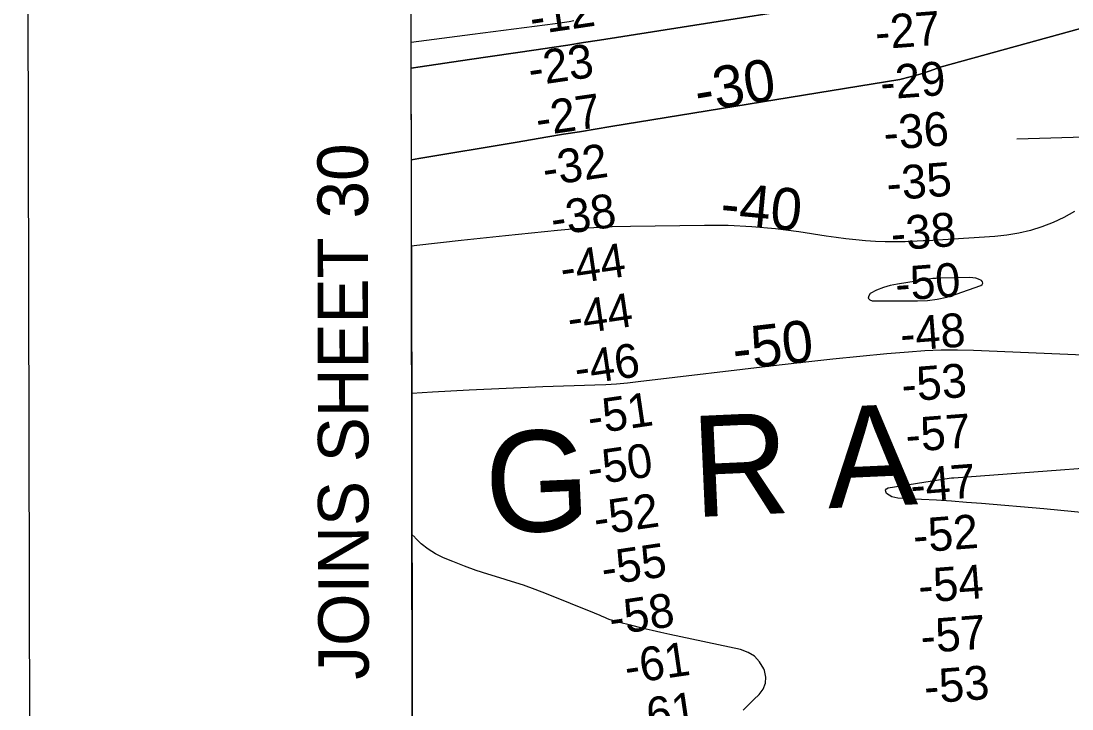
# Model space of a CAD drawing. Extents: x 3329332 to 3367211, y 631066 to 656469.
# Drawn here: x 3332666 to 3334750, y 646478 to 647841 of the extents above; entities that cross this region are included whole.
import ezdxf

# ---------------------------------------------------------------- set-up
doc = ezdxf.new("R2010")
doc.units = 0
for name, color, linetype in [('V-ANNO-SYMB', 7, 'Continuous'), ('V-ANNO-TEXT', 7, 'Continuous'), ('V-GRID-FRAM', 7, 'Continuous'), ('V-RIVR-EDGE', 7, 'Continuous'), ('V-RIVR-IDEN', 7, 'Continuous'), ('V-RIVR-RANG', 7, 'Continuous'), ('V-STRM-FLOW', 7, 'Continuous'), ('V-TOPO-DPTH', 7, 'Continuous'), ('V-TOPO-MAJR', 7, 'Continuous'), ('V-TOPO-MAJR-IDEN', 7, 'Continuous'), ('V-TOPO-MINR', 7, 'Continuous'), ('V-TOPO-MINR-IDEN', 7, 'Continuous')]:
    doc.layers.add(name, color=color, linetype=linetype)

msp = doc.modelspace()

# ---------------------------------------------------------------- linework, layer by layer
at = {"layer": 'V-ANNO-SYMB'}
msp.add_lwpolyline([(3332709.6, 632280), (3365792.7, 632342.5), (3365749.4, 655259), (3332666.3, 655196.5), (3332709.6, 632280)], dxfattribs=at)
at = {"layer": 'V-GRID-FRAM'}
msp.add_lwpolyline([(3333429.9, 654632), (3364987.9, 654691.7), (3365030.2, 636507.7), (3333456.4, 636448), (3333429.9, 654632)], dxfattribs=at)
at = {"layer": 'V-RIVR-EDGE'}
msp.add_spline([(3343636.8, 646843.4), (3343622.1, 646851.6), (3343608.9, 646858.6), (3343596.5, 646861.3), (3343585.3, 646861.8), (3343568.2, 646866.8), (3343554.7, 646877.7), (3343538.1, 646892.1), (3343529.1, 646895.6), (3343519.5, 646901.9), (3343506.7, 646910), (3343488.9, 646921.3), (3343476.1, 646929.9), (3343464.1, 646937.3), (3343456.7, 646944.3), (3343449.8, 646951.3), (3343444.7, 646953.2), (3343437.4, 646956), (3343425, 646958.3), (3343409.5, 646962.2), (3343396.7, 646968.1), (3343383.5, 646974.3), (3343375.8, 646976.7), (3343358.7, 646980.2), (3343342.4, 646984.1), (3343325, 646985.3), (3343315.3, 646986.5), (3343304.8, 646990.4), (3343289, 646998.6), (3343275.4, 647006.8), (3343265, 647012.6), (3343248.7, 647018.5), (3343234, 647022.4), (3343209.9, 647028.3), (3343162.3, 647042.4), (3343147.9, 647045.1), (3343128.9, 647049.4), (3343116.5, 647051.8), (3343106.5, 647056.8), (3343102.6, 647058.8), (3343086.7, 647062.3), (3343081.3, 647062.3), (3343073.5, 647063.9), (3343064.6, 647066.2), (3343053.7, 647071.7), (3343047.9, 647075.6), (3343041.7, 647078.3), (3343029.3, 647083), (3343020, 647087.7), (3343006.5, 647095.1), (3342971.6, 647108), (3342951.5, 647116.6), (3342937.2, 647125.1), (3342928.2, 647130.6), (3342903.1, 647138.8), (3342877.5, 647148.5), (3342858.9, 647157.5), (3342849.6, 647166.1), (3342844.2, 647170.7), (3342831.8, 647175.4), (3342823.7, 647177.8), (3342803.9, 647181.7), (3342796.5, 647184.4), (3342787.2, 647189.5), (3342775.6, 647194.6), (3342758.9, 647198.9), (3342733, 647203.6), (3342721.3, 647205.9), (3342697.7, 647211.8), (3342664, 647222), (3342635.7, 647232.1), (3342620.6, 647237.2), (3342602, 647239.2), (3342563.6, 647249.4), (3342526.8, 647258.8), (3342490.8, 647270.9), (3342457.1, 647284.1), (3342444.7, 647290), (3342438, 647274.1), (3342415.2, 647281.5), (3342391.9, 647292.1), (3342329.2, 647319.8), (3342295.1, 647333.8), (3342283.1, 647338.9), (3342254.8, 647352.1), (3342236.2, 647360.3), (3342218.4, 647367.3), (3342205.2, 647372.8), (3342191.6, 647379.4), (3342179.3, 647387.6), (3342172.3, 647390.7), (3342149.8, 647402), (3342116.9, 647419.2), (3342096.4, 647427.4), (3342074.7, 647436.7), (3342056.5, 647442.2), (3342048.7, 647445.3), (3342046.4, 647448), (3342044.5, 647450.4), (3342038.3, 647452.7), (3342007.6, 647462.5), (3341964.2, 647476.9), (3341952.2, 647483.6), (3341946, 647485.5), (3341937.1, 647486.3), (3341928.6, 647486.7), (3341922.4, 647489.8), (3341906.5, 647496.5), (3341894.5, 647501.9), (3341878.2, 647510.1), (3341870.1, 647509.7), (3341856.9, 647512.1), (3341848, 647514.5), (3341827.1, 647520.3), (3341821.3, 647523.4), (3341814.7, 647526.6), (3341810, 647526.6), (3341806.5, 647525.8), (3341795.3, 647527), (3341774.7, 647530.5), (3341748.8, 647539.9), (3341739.1, 647543.8), (3341723.2, 647545.8), (3341703.4, 647550.1), (3341688.7, 647553.2), (3341675.1, 647556.4), (3341665.1, 647559.5), (3341655.8, 647566.5), (3341650.4, 647570.8), (3341641.1, 647573.1), (3341619.4, 647577.5), (3341603.1, 647581), (3341588.7, 647581), (3341577.9, 647580.3), (3341570.5, 647581.8), (3341563.9, 647584.6), (3341550.4, 647590.8), (3341537.2, 647595.5), (3341512, 647602.9), (3341494.2, 647606.9), (3341474, 647611.9), (3341452.3, 647619.4), (3341435.6, 647623.7), (3341426.7, 647624.1), (3341409.7, 647627.6), (3341399.6, 647628.4), (3341382.2, 647633.9), (3341364.3, 647640.9), (3341355.4, 647643.3), (3341344.2, 647645.2), (3341336, 647644.9), (3341320.5, 647646.4), (3341290.7, 647651.2), (3341274, 647656.3), (3341268.6, 647656.7), (3341257, 647656.3), (3341232.5, 647658.7), (3341212, 647661.8), (3341186, 647668.9), (3341159.7, 647674), (3341146.5, 647674.8), (3341117, 647677.6), (3341103.4, 647677.2), (3341097.6, 647677.2), (3341091.8, 647678.8), (3341087.9, 647680.8), (3341085.2, 647682.7), (3341079.8, 647684.7), (3341055.4, 647685.9), (3341036.4, 647687.5), (3341024.7, 647686), (3341011.2, 647684.8), (3340999.5, 647686.8), (3340985.2, 647690.3), (3340953.8, 647701.3), (3340935.6, 647709.1), (3340923.6, 647714.5), (3340917, 647718.4), (3340910.8, 647718.4), (3340908.1, 647717.3), (3340903.8, 647717.3), (3340894.5, 647718.5), (3340882.5, 647719.3), (3340860.8, 647726.3), (3340855.8, 647729.8), (3340851.9, 647734.5), (3340848.4, 647736.8), (3340842.6, 647737.6), (3340826.3, 647742.3), (3340811.6, 647748.9), (3340794.9, 647758.7), (3340781.4, 647769.2), (3340774.8, 647778.9), (3340770.9, 647778.9), (3340766.3, 647782), (3340765.2, 647787.8), (3340765.2, 647791.3), (3340761.7, 647794.8), (3340748.9, 647800.7), (3340736.9, 647803.8), (3340725.3, 647807.3), (3340719.4, 647809.6), (3340716.4, 647813.1), (3340707.8, 647818.2), (3340686.5, 647829.9), (3340661, 647840.4), (3340654.4, 647842.4), (3340636.6, 647848.2), (3340626.5, 647851), (3340619.1, 647851), (3340608.2, 647849.1), (3340603.2, 647848.7), (3340600.5, 647851.1), (3340597.8, 647853.8), (3340589.6, 647855.3), (3340581.5, 647857.7), (3340569.1, 647863.9), (3340561.4, 647869), (3340557.9, 647873.6), (3340534.6, 647880.7), (3340500.5, 647891.6), (3340470.7, 647900.2), (3340445.5, 647911.2), (3340419.6, 647920.5), (3340404.1, 647927.5), (3340372.7, 647939.6), (3340342.5, 647952.9), (3340306.1, 647969.7), (3340282.8, 647985.6), (3340275.1, 647994.2), (3340268.9, 647998.8), (3340258.8, 648001.2), (3340240.2, 648007.1), (3340208.8, 648017.2), (3340162.7, 648036.7), (3340150.3, 648044.9), (3340132.9, 648056.2), (3340120.1, 648064.4), (3340103.9, 648071.8), (3340062.4, 648085.1), (3340020.6, 648097.2), (3340008.2, 648099.9), (3339970.6, 648113.2), (3339931.4, 648129.2), (3339890, 648138.2), (3339851.6, 648144.1), (3339826.8, 648151.2), (3339779.1, 648166), (3339750.5, 648177), (3339726.4, 648186.7), (3339710.2, 648194.1), (3339698.6, 648200), (3339685, 648204.7), (3339657.5, 648210.2), (3339640.4, 648209.4), (3339598.1, 648212.2), (3339566.4, 648218.9), (3339519.1, 648229.1), (3339492.7, 648236.9), (3339468.3, 648244.8), (3339451.6, 648247.9), (3339423.7, 648249.9), (3339391.1, 648250.4), (3339356.3, 648256.7), (3339323.3, 648262.2), (3339267.1, 648267), (3339191.5, 648276.1), (3339142.6, 648283.6), (3339080.6, 648294.2), (3339050, 648300.1), (3339012.8, 648305.2), (3338936.4, 648315.1), (3338861.6, 648324.6), (3338841, 648325.8), (3338779.4, 648333.3), (3338717, 648341.2), (3338619.7, 648351.2), (3338573.9, 648357.9), (3338540.2, 648363.4), (3338502.2, 648370.5), (3338454.1, 648371.4), (3338406, 648373.4), (3338372.7, 648373.9), (3338327.7, 648378.3), (3338302.9, 648381.4), (3338283.5, 648380.7), (3338273.8, 648381.5), (3338260.7, 648386.6), (3338248.6, 648391.6), (3338238.6, 648396.3), (3338223.5, 648397.5), (3338149.4, 648404.7), (3338106.8, 648411), (3338090.5, 648416.9), (3338075.8, 648425.4), (3338068, 648428.5), (3338061, 648430.1), (3338050.2, 648432.5), (3338042.1, 648437.1), (3338023.1, 648446.5), (3338014.2, 648455.1), (3338009.5, 648464.4), (3338008, 648470.6), (3338005.7, 648475.6), (3338000.3, 648481.5), (3337993.3, 648485), (3337977.8, 648485), (3337963.8, 648486.6), (3337952.2, 648492.4), (3337934.8, 648503.3), (3337924.4, 648514.6), (3337915.5, 648527.8), (3337907, 648538.3), (3337897.7, 648544.1), (3337885.7, 648546.1), (3337868.6, 648552.4), (3337833.7, 648570.3), (3337831.4, 648572.6), (3337828.3, 648579.6), (3337825.3, 648586.6), (3337821.8, 648591.3), (3337805.1, 648601.8), (3337772.2, 648615.4), (3337745.1, 648623.2), (3337725.3, 648627.6), (3337697.4, 648633.4), (3337655.9, 648643.2), (3337633.1, 648645.2), (3337587.7, 648647.3), (3337530.7, 648646.3), (3337482.2, 648645.6), (3337469.4, 648646), (3337459.3, 648649.5), (3337449.6, 648650.7), (3337426, 648650.8), (3337387.2, 648648.6), (3337346.1, 648646), (3337294.5, 648642.2), (3337235.9, 648635), (3337203.7, 648632), (3337180.8, 648629.7), (3337120.3, 648621.3), (3337079.6, 648613.3), (3337042, 648609.5), (3337018.3, 648606.8), (3336982.6, 648599.1), (3336951.6, 648594.2), (3336908.5, 648592.7), (3336875.2, 648597.1), (3336858.1, 648598.3), (3336851.1, 648601), (3336844.9, 648603.4), (3336839.1, 648604.2), (3336831, 648604.2), (3336822, 648601.1), (3336811.6, 648595.3), (3336803, 648593.4), (3336796, 648593), (3336789.1, 648595.4), (3336779.4, 648595.8), (3336757.3, 648590.8), (3336729.7, 648577.7), (3336702.1, 648570), (3336685.9, 648570.4), (3336673.8, 648572), (3336663.7, 648571.2), (3336652.9, 648568.2), (3336637, 648559.3), (3336627.3, 648556.6), (3336614.5, 648555.9), (3336585, 648551.7), (3336546.2, 648547.9), (3336510.1, 648542.1), (3336477.9, 648535.2), (3336448.4, 648524.8), (3336423.9, 648508.6), (3336410.7, 648494.7), (3336400.6, 648480.4), (3336397.5, 648469.1), (3336394.7, 648454), (3336388.1, 648437.7), (3336381.5, 648423.4), (3336376, 648411), (3336372.5, 648404), (3336364.3, 648397.9), (3336361.2, 648394.8), (3336359.7, 648392.1), (3336357.7, 648385.9), (3336351.1, 648378.5), (3336344.9, 648364.6), (3336339.8, 648359.9), (3336331.3, 648357.2), (3336326.2, 648354.5), (3336319.2, 648349.9), (3336309.9, 648341), (3336302.5, 648337.5), (3336295.1, 648333.3), (3336287, 648324.8), (3336280.4, 648321.7), (3336267.2, 648317.4), (3336257.9, 648317.5), (3336251.7, 648317.5), (3336242.4, 648316.7), (3336231.5, 648316), (3336219.9, 648316), (3336194.7, 648315.7), (3336165.6, 648319.6), (3336148.1, 648318.9), (3336131.1, 648316.6), (3336112, 648312.4), (3336101.9, 648308.9), (3336086.4, 648300), (3336075.5, 648296.2), (3336060.4, 648293.9), (3336047.6, 648294.3), (3336032.5, 648298.2), (3336021.7, 648301.8), (3336016.2, 648303.3), (3336006.5, 648303.7), (3335978.6, 648305.7), (3335940.2, 648301.2), (3335891.7, 648295.1), (3335848.7, 648290.5), (3335790.1, 648290.3), (3335753.3, 648290), (3335726.5, 648286.2), (3335694.7, 648282.8), (3335674.9, 648275.9), (3335659.4, 648272.4), (3335636.5, 648268.6), (3335620.6, 648266.7), (3335591.9, 648266), (3335557.8, 648268), (3335544.2, 648268), (3335523.2, 648266.9), (3335504.6, 648263.9), (3335489.9, 648262), (3335466.2, 648265.5), (3335442.2, 648264.8), (3335411.6, 648264.9), (3335377.8, 648261.9), (3335309.1, 648254.7), (3335266.5, 648252.4), (3335244, 648251.3), (3335220.7, 648250.6), (3335202.5, 648253), (3335190.1, 648253), (3335171.1, 648250.7), (3335140, 648245.4), (3335097.7, 648231.9), (3335079.9, 648228.5), (3335074.8, 648228.5), (3335068.6, 648228.1), (3335061.7, 648228.1), (3335052.3, 648225.8), (3335042.3, 648224.3), (3335032.2, 648218.9), (3335022.1, 648215.8), (3335003.1, 648212.8), (3334965.8, 648211.3), (3334950.7, 648212.5), (3334915.8, 648214.9), (3334852.2, 648213.5), (3334793.3, 648210.2), (3334744.8, 648208.3), (3334710.6, 648207.3), (3334677.3, 648204.6), (3334638.5, 648204.3), (3334608.6, 648204.8), (3334566.8, 648205.7), (3334543.1, 648205.7), (3334524.9, 648204.6), (3334499.7, 648202.7), (3334450.4, 648202.5), (3334410.5, 648202.6), (3334380.2, 648202.7), (3334353.9, 648206.2), (3334344.6, 648205.5), (3334325.6, 648204), (3334283.3, 648200.2), (3334254.6, 648197.2), (3334219.3, 648193.7), (3334183.2, 648192.7), (3334158.4, 648191.6), (3334149.5, 648191.2), (3334137, 648188.1), (3334128.5, 648185.4), (3334111, 648182.8), (3334081.6, 648179.7), (3334057.1, 648178.6), (3334040.8, 648179.5), (3334030, 648183), (3334019.9, 648183), (3333987.3, 648177.3), (3333955.1, 648172.7), (3333933, 648170.8), (3333909, 648171.2), (3333889.6, 648172.5), (3333868.3, 648173.3), (3333818.6, 648173.4), (3333772.1, 648172), (3333733.7, 648169.4), (3333687.9, 648167.5), (3333648, 648163.4), (3333617.3, 648159.6), (3333590.5, 648153), (3333562.6, 648148.1), (3333531.6, 648141.5), (3333511, 648139.7), (3333488.9, 648138.2), (3333475.7, 648137.8), (3333461.7, 648134.7), (3333439.4, 648130.1)], degree=3, dxfattribs=at)
at = {"layer": 'V-STRM-FLOW'}
msp.add_line((3334640.3, 647607.7), (3334890.6, 647615.7), dxfattribs=at)
at = {"layer": 'V-TOPO-DPTH'}
for points in [[(3335147.6, 647931.8), (3334488.3, 647749.7), (3334468.7, 647742.6), (3334448.9, 647736.1), (3334428.8, 647730.6), (3334408.5, 647725.7), (3333835.8, 647632.1), (3333804.5, 647627.1), (3333773.1, 647622), (3333741.8, 647616.8), (3333710.5, 647611.6), (3333645.8, 647600.8), (3333582.2, 647590.1), (3333518.6, 647579.4), (3333454.9, 647568.7), (3333440.2, 647566.2), (3333440, 647748)], [(3333440.2, 647566.2), (3333454.9, 647568.7), (3333518.6, 647579.4), (3333582.2, 647590.1), (3333645.8, 647600.8), (3333710.5, 647611.6), (3333741.8, 647616.8), (3333773.1, 647622), (3333804.5, 647627.1), (3333835.8, 647632.1), (3334408.5, 647725.7), (3334428.8, 647730.6), (3334448.9, 647736.1), (3334468.7, 647742.6), (3334488.3, 647749.7), (3335147.6, 647931.8)], [(3334434.5, 647901.6), (3333812.9, 647803.3), (3333781.5, 647798.5), (3333750.1, 647793.7), (3333718.7, 647789.1), (3333687.3, 647784.4), (3333555, 647765), (3333457.5, 647750.6), (3333440, 647748), (3333439.8, 647885)], [(3333440, 647748), (3333457.5, 647750.6), (3333555, 647765), (3333687.3, 647784.4), (3333718.7, 647789.1), (3333750.1, 647793.7), (3333781.5, 647798.5), (3333812.9, 647803.3), (3334434.5, 647901.6)], [(3334754.5, 647463.7), (3334733.7, 647452.2), (3334712.1, 647442.3), (3334689.9, 647433.5), (3334667.1, 647426.4), (3334644, 647420.7), (3334620.5, 647416.8), (3334596.8, 647414.3), (3334493.5, 647407.5), (3334483.8, 647406.9), (3334474, 647406.4), (3334464.3, 647405.9), (3334454.6, 647405.4), (3334418.9, 647403.9), (3334399.2, 647403.5), (3334379.6, 647403.5), (3334360, 647404.3), (3334340.4, 647405.7), (3334320.9, 647407.6), (3334301.4, 647409.7), (3334281.9, 647412.3), (3334262.4, 647415), (3334208.2, 647423.3), (3334161.6, 647429.3), (3334114.9, 647433.7), (3334068, 647435.8), (3334021, 647436.3), (3333874.4, 647434.3), (3333838.2, 647433.3), (3333802.1, 647431.7), (3333766, 647429.2), (3333729.9, 647425.9), (3333626.5, 647415.4), (3333538.8, 647406.1), (3333451.1, 647396.5), (3333440.5, 647395.3), (3333440.2, 647566.2)], [(3334754.5, 647463.7), (3334733.7, 647452.2), (3334712.1, 647442.3), (3334689.9, 647433.5), (3334667.1, 647426.4), (3334644, 647420.7), (3334620.5, 647416.8), (3334596.8, 647414.3), (3334493.5, 647407.5), (3334483.8, 647406.9), (3334474, 647406.4), (3334464.3, 647405.9), (3334454.6, 647405.4), (3334418.9, 647403.9), (3334399.2, 647403.5), (3334379.6, 647403.5), (3334360, 647404.3), (3334340.4, 647405.7), (3334320.9, 647407.6), (3334301.4, 647409.7), (3334281.9, 647412.3), (3334262.4, 647415), (3334208.2, 647423.3), (3334161.6, 647429.3), (3334114.9, 647433.7), (3334068, 647435.8), (3334021, 647436.3), (3333874.4, 647434.3), (3333838.2, 647433.3), (3333802.1, 647431.7), (3333766, 647429.2), (3333729.9, 647425.9), (3333626.5, 647415.4), (3333538.8, 647406.1), (3333451.1, 647396.5), (3333440.5, 647395.3)], [(3333440.5, 647395.3), (3333442.3, 646140.6), (3333554.9, 646132.4), (3333627.2, 646128.3), (3333699.6, 646125.7), (3333772, 646125.5), (3333844.4, 646126.8), (3333946.8, 646130.4), (3333968.1, 646131.1), (3333989.3, 646131.9), (3334010.5, 646132.8), (3334588.9, 646111.7), (3334669.5, 646114.8), (3334719, 646116.9), (3334768.4, 646119.4)]]:
    msp.add_lwpolyline(points, dxfattribs=at)
at = {"layer": 'V-TOPO-MAJR'}
for points in [[(3334375.7, 647313.2), (3334362.4, 647307.7), (3334349.6, 647301.1), (3334346.6, 647296.4), (3334345.9, 647292.3), (3334348.6, 647289.1), (3334353.5, 647286.5), (3334443.5, 647286.6), (3334463, 647287.6), (3334482.4, 647289.9), (3334501.4, 647294.2), (3334520.2, 647299.7), (3334569.2, 647317), (3334571.7, 647319.3), (3334572.9, 647321.8), (3334572.1, 647324.4), (3334570.1, 647327.1), (3334564.6, 647329.7), (3334559, 647331.6), (3334553.2, 647332.6), (3334547.1, 647333), (3334485.2, 647331.7), (3334482.4, 647331.6), (3334479.6, 647331.4), (3334476.8, 647331.1), (3334474.1, 647330.8), (3334403.6, 647320.1), (3334389.4, 647317.2), (3334375.7, 647313.2)], [(3334896.6, 647173.8), (3334554.6, 647188.2), (3334522.4, 647188.9), (3334490.2, 647188.8), (3334458, 647187.5), (3334425.8, 647185.3), (3334382.9, 647181.5), (3334329.3, 647176.6), (3334275.8, 647171.3), (3334222.3, 647165.5), (3334168.9, 647159.4), (3333889.9, 647126), (3333868.4, 647123.7), (3333846.9, 647121.8), (3333825.3, 647120.4), (3333803.7, 647119.4), (3333700.8, 647116.1), (3333627.7, 647113.4), (3333554.7, 647110.1), (3333481.7, 647106), (3333440.9, 647103.4)], [(3334782, 646866.3), (3334693.8, 646874.6), (3334570.4, 646885), (3334540.6, 646887.4), (3334510.8, 646889.6), (3334481, 646891.6), (3334451.2, 646893.4), (3334404.4, 646896), (3334398.3, 646897), (3334392.4, 646898.7), (3334387, 646901.6), (3334382, 646905.3), (3334380.4, 646908.7), (3334380.1, 646911.6), (3334381.9, 646914), (3334385.1, 646916), (3334497.7, 646934.3), (3334502.1, 646935), (3334506.5, 646935.5), (3334510.9, 646936), (3334515.3, 646936.4), (3334973.5, 646970.7)]]:
    msp.add_lwpolyline(points, dxfattribs=at)
at = {"layer": 'V-TOPO-MINR'}
for points in [[(3335147.6, 647931.8), (3334488.3, 647749.7), (3334468.7, 647742.6), (3334448.9, 647736.1), (3334428.8, 647730.6), (3334408.5, 647725.7), (3333835.8, 647632.1), (3333804.5, 647627.1), (3333773.1, 647622), (3333741.8, 647616.8), (3333710.5, 647611.6), (3333645.8, 647600.8), (3333582.2, 647590.1), (3333518.6, 647579.4), (3333454.9, 647568.7), (3333440.2, 647566.2)], [(3334434.5, 647901.6), (3333812.9, 647803.3), (3333781.5, 647798.5), (3333750.1, 647793.7), (3333718.7, 647789.1), (3333687.3, 647784.4), (3333555, 647765), (3333457.5, 647750.6), (3333440, 647748)], [(3333762, 647841.5), (3333752.9, 647839.9), (3333743.7, 647838.4), (3333734.5, 647837), (3333725.3, 647835.7), (3333561.1, 647814.4), (3333469.8, 647802.6), (3333439.9, 647798.8)], [(3334754.5, 647463.7), (3334733.7, 647452.2), (3334712.1, 647442.3), (3334689.9, 647433.5), (3334667.1, 647426.4), (3334644, 647420.7), (3334620.5, 647416.8), (3334596.8, 647414.3), (3334493.5, 647407.5), (3334483.8, 647406.9), (3334474, 647406.4), (3334464.3, 647405.9), (3334454.6, 647405.4), (3334418.9, 647403.9), (3334399.2, 647403.5), (3334379.6, 647403.5), (3334360, 647404.3), (3334340.4, 647405.7), (3334320.9, 647407.6), (3334301.4, 647409.7), (3334281.9, 647412.3), (3334262.4, 647415), (3334208.2, 647423.3), (3334161.6, 647429.3), (3334114.9, 647433.7), (3334068, 647435.8), (3334021, 647436.3), (3333874.4, 647434.3), (3333838.2, 647433.3), (3333802.1, 647431.7), (3333766, 647429.2), (3333729.9, 647425.9), (3333626.5, 647415.4), (3333538.8, 647406.1), (3333451.1, 647396.5), (3333440.5, 647395.3)], [(3334098, 646475.4), (3334108.2, 646486.2), (3334118.7, 646496.7), (3334129.5, 646506.9), (3334137.3, 646517.6), (3334142.2, 646529), (3334142.6, 646541.4), (3334139.9, 646554.4), (3334138.5, 646557.9), (3334130.3, 646571.4), (3334120.3, 646582.5), (3334107.5, 646590.3), (3334092.8, 646595.9), (3333952.4, 646625.6), (3333934.8, 646629.4), (3333917.2, 646633.4), (3333899.7, 646637.7), (3333882.2, 646642), (3333844.8, 646651.6), (3333839.3, 646653.2), (3333834, 646654.9), (3333828.7, 646656.9), (3333823.5, 646659.2), (3333818.4, 646661.5), (3333813.2, 646663.8), (3333808, 646666), (3333802.8, 646668.1), (3333708.2, 646706.3), (3333685.2, 646715.1), (3333662.1, 646723.5), (3333638.7, 646731), (3333615.2, 646738), (3333591.7, 646745.1), (3333568.3, 646752.7), (3333545.2, 646761.1), (3333522.4, 646770.1), (3333503.5, 646777.9), (3333487.9, 646785.6), (3333473.2, 646794.6), (3333459.8, 646805.4), (3333447.4, 646817.5), (3333446.7, 646818.3), (3333441.3, 646823.6)]]:
    msp.add_lwpolyline(points, dxfattribs=at)

# ---------------------------------------------------------------- texts
at = {"layer": 'V-ANNO-TEXT'}
msp.add_text('JOINS SHEET 30', height=100, rotation=90.1083, dxfattribs=at).set_placement((3333355.7, 646536.1))
at = {"layer": 'V-RIVR-IDEN'}
for s, p in [('A', (3334266.8, 646875.8)), ('R', (3334000.3, 646858.1)), ('G', (3333590.2, 646825.1))]:
    msp.add_text(s, height=200, rotation=2.5699, dxfattribs=at).set_placement(p)
at = {"layer": 'V-RIVR-RANG'}
for s, rotation, p in [('-12', 8.33, (3333679.4, 647813.6)), ('-27', 4.4038, (3334361.6, 647784.8)), ('-23', 8.33, (3333676.4, 647712.1)), ('-29', 4.4038, (3334371.9, 647685.3)), ('-27', 8.33, (3333691.2, 647613.2)), ('-36', 4.4038, (3334378.5, 647585.5)), ('-32', 8.33, (3333704.9, 647514.2)), ('-35', 4.4038, (3334384.4, 647485.6)), ('-38', 8.33, (3333721.2, 647415.5)), ('-38', 4.4038, (3334392.9, 647386)), ('-44', 8.33, (3333739.9, 647317.1)), ('-50', 4.4038, (3334401.6, 647286.4)), ('-44', 8.33, (3333754.1, 647218.2)), ('-48', 4.4038, (3334411.4, 647186.8)), ('-46', 8.33, (3333768.1, 647119.1)), ('-53', 4.4038, (3334414.1, 647086.7)), ('-51', 8.33, (3333794.1, 647021.9)), ('-57', 4.4038, (3334422.1, 646987)), ('-50', 8.33, (3333793.7, 646920.8)), ('-47', 4.4038, (3334431.6, 646887.5)), ('-52', 8.33, (3333806.2, 646821.5)), ('-52', 4.4038, (3334436.9, 646787.6)), ('-55', 8.33, (3333821.4, 646722.7)), ('-54', 4.4038, (3334447.2, 646688.1)), ('-58', 8.33, (3333836.7, 646623.9)), ('-57', 4.4038, (3334451.8, 646588.2)), ('-61', 8.33, (3333867.4, 646527.3)), ('-53', 4.4038, (3334458.7, 646488.4)), ('-61', 8.33, (3333881.7, 646428.3))]:
    msp.add_text(s, height=67, rotation=rotation, dxfattribs=at).set_placement(p)
at = {"layer": 'V-TOPO-MAJR-IDEN'}
msp.add_text('-50', height=83, rotation=6.5542, dxfattribs=at).set_placement((3334081.1, 647149.3))
at = {"layer": 'V-TOPO-MINR-IDEN'}
for s, rotation, p in [('-30', 9.2783, (3334008.2, 647660.3)), ('-40', 354.6128, (3334050.6, 647439.8))]:
    msp.add_text(s, height=83, rotation=rotation, dxfattribs=at).set_placement(p)

doc.saveas('drawing.dxf')
